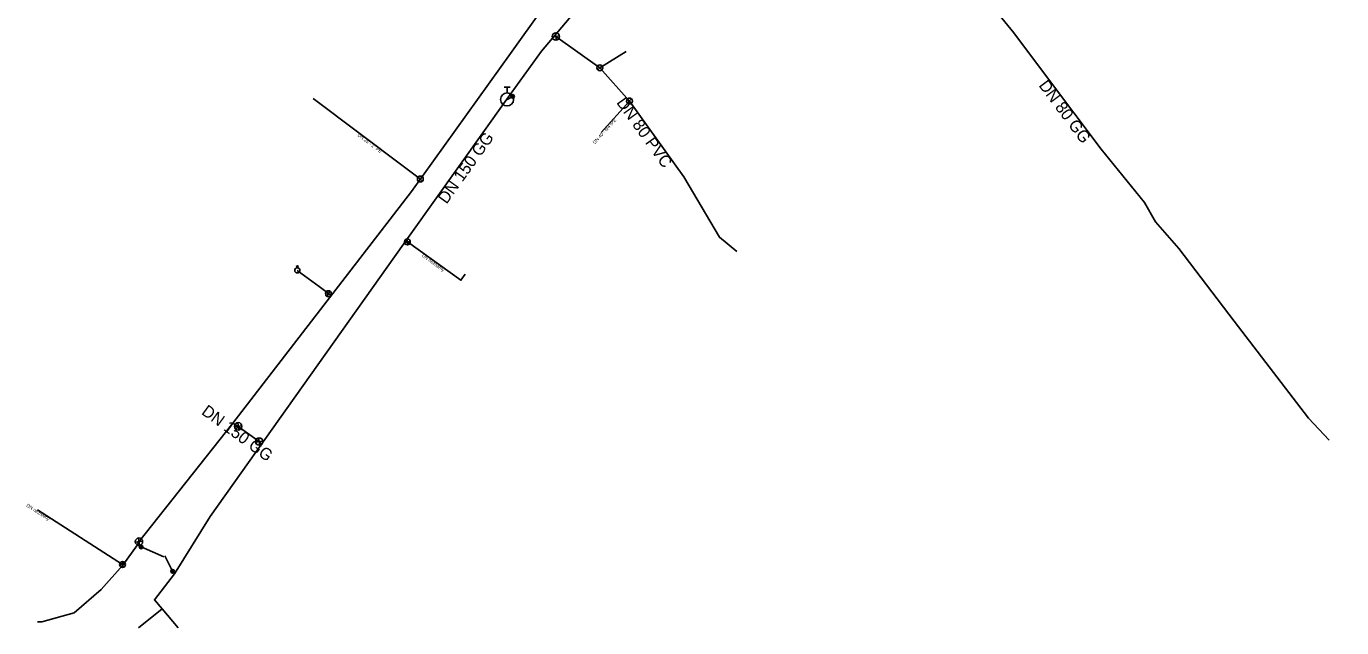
# Model space of a CAD drawing. Extents: x -4927528 to -4924018, y -11264917 to -11262544.
# Drawn here: x -4927528 to -4925742, y -11264917 to -11264100 of the extents above; entities that cross this region are included whole.
import ezdxf

# ---------------------------------------------------------------- set-up
doc = ezdxf.new("R2010")
doc.units = 0
for name, color, linetype in [('_hydrantova_odbocka_', 7, 'Continuous'), ('_kalosvod_', 7, 'Continuous'), ('_pripojka_prevzato_z_dokumentace_', 7, 'Continuous'), ('_pripojka_priblizne_', 7, 'Continuous'), ('_voda_smvak_prevzato_z_dokumentace_', 7, 'Continuous'), ('_voda_smvak_priblizne_', 7, 'Continuous'), ('Default', 7, 'Continuous'), ('MoLevel 2', 7, 'Continuous'), ('MoLevel 27', 7, 'Continuous'), ('MoLevel 28', 7, 'Continuous'), ('MoLevel 30', 7, 'Continuous'), ('MoLevel 32', 7, 'Continuous'), ('MoLevel 46', 7, 'Continuous'), ('MoLevel 53', 7, 'Continuous'), ('MoLevel 55', 7, 'Continuous')]:
    doc.layers.add(name, color=color, linetype=linetype)

# ---------------------------------------------------------------- blocks, each defined once
blk = doc.blocks.new('_uzaver_')
at = {"layer": 'Default'}
for p, q in [((-0.00035, -0.00035), (0.00035, 0.00035)), ((0.00035, -0.00035), (-0.00035, 0.00035))]:
    blk.add_line(p, q, dxfattribs=at)
for radius in [0.0005, 0.000025]:
    blk.add_circle((0, 0), radius, dxfattribs=at)
blk = doc.blocks.new('_uzaver_pripojka_')
at = {"layer": 'Default'}
for p, q in [((-0.00035, -0.00035), (0.00035, 0.00035)), ((0.00035, -0.00035), (-0.00035, 0.00035))]:
    blk.add_line(p, q, dxfattribs=at)
for radius in [0.0005, 0.000025]:
    blk.add_circle((0, 0), radius, dxfattribs=at)
blk = doc.blocks.new('_hydrant_voda_')
at = {"layer": 'Default'}
for p, q in [((-0.000225, 0.00095), (0.000225, 0.00095)), ((0, 0.00095), (0, 0.0005))]:
    blk.add_line(p, q, dxfattribs=at)
blk.add_circle((0, 0), 0.0005, dxfattribs=at)
blk = doc.blocks.new('_sachta_voda_')
at = {"layer": 'Default'}
blk.add_lwpolyline([(-0.0001, 0.00065), (0, 0.00035), (0.0001, 0.00065)], dxfattribs=at)
blk.add_circle((0, 0), 0.00035, dxfattribs=at)

msp = doc.modelspace()

# ---------------------------------------------------------------- linework, layer by layer
at = {"layer": '_hydrantova_odbocka_'}
msp.add_lwpolyline([(-4926870.9, -11264193.9), (-4926867.8, -11264195.4), (-4926875.4, -11264199.6)], dxfattribs=at)
at = {"layer": '_kalosvod_'}
for p, q in [((-4927372.5, -11264807.1), (-4927341.5, -11264820.7)), ((-4927329.7, -11264840.2), (-4927340.3, -11264819.1))]:
    msp.add_line(p, q, dxfattribs=at)
at = {"layer": '_pripojka_prevzato_z_dokumentace_'}
for p, q in [((-4927014.7, -11264291.5), (-4927138.7, -11264198.4)), ((-4926993.2, -11264307.6), (-4927014.7, -11264291.5)), ((-4927513.4, -11264756.6), (-4927397.6, -11264831)), ((-4927397.6, -11264831), (-4927397.1, -11264831.8))]:
    msp.add_line(p, q, dxfattribs=at)
msp.add_lwpolyline([(-4927012.9, -11264391.7), (-4927010.8, -11264393), (-4926938.1, -11264445.1), (-4926932.3, -11264437)], dxfattribs=at)
at = {"layer": '_pripojka_priblizne_'}
for p, q in [((-4926749.4, -11264156.5), (-4926713.7, -11264134.4)), ((-4926709.2, -11264201.7), (-4926747.6, -11264244.3)), ((-4927130.8, -11264453.7), (-4927160.3, -11264431.6))]:
    msp.add_line(p, q, dxfattribs=at)
msp.add_lwpolyline([(-4927114.6, -11264466.2), (-4927118.1, -11264463.2), (-4927130.8, -11264453.7)], dxfattribs=at)
at = {"layer": '_voda_smvak_prevzato_z_dokumentace_'}
for p, q in [((-4927375.4, -11264800), (-4927377.2, -11264804.4)), ((-4927377.2, -11264804.4), (-4927372.5, -11264807.1)), ((-4927329.7, -11264840.2), (-4927326.9, -11264843.6)), ((-4927376, -11264916.8), (-4927344, -11264891.3)), ((-4927344, -11264891.3), (-4927322.3, -11264916.8))]:
    msp.add_line(p, q, dxfattribs=at)
for points in [[(-4925741.8, -11263257.7), (-4926471.3, -11263779.7), (-4926626.3, -11263906.7), (-4926783.8, -11264042.7), (-4926826.3, -11264075.2), (-4926870.7, -11264137), (-4927005.3, -11264324.4), (-4927247.9, -11264639.2), (-4927375.4, -11264800)], [(-4926437.3, -11263792.5), (-4926527.5, -11263855.5), (-4926618.2, -11263919.4), (-4926768.5, -11264062.5), (-4926828.7, -11264133.9), (-4926875.7, -11264199.1), (-4927006, -11264381.9), (-4927278.6, -11264765.7), (-4927326.9, -11264843.6)], [(-4925759, -11264662.1), (-4925786.7, -11264632.1), (-4925887.7, -11264500.4), (-4925963.1, -11264402.1), (-4925994.9, -11264365.7), (-4926009.6, -11264339.3), (-4926068.7, -11264267.1), (-4926142.6, -11264168.2), (-4926187.3, -11264109.2), (-4926252.4, -11264029.2), (-4926261.4, -11264017.3), (-4926383.4, -11263863.6), (-4926433.6, -11263797)], [(-4926809.1, -11264114.1), (-4926749.4, -11264156.5), (-4926709.2, -11264201.7), (-4926635.4, -11264304.7), (-4926586.8, -11264386.6), (-4926563.3, -11264405.8)], [(-4927377.2, -11264804.4), (-4927397.1, -11264831.8), (-4927426.8, -11264865.1), (-4927463.4, -11264896.8), (-4927507.4, -11264908.9), (-4927513.4, -11264909)], [(-4927326.9, -11264843.6), (-4927354.4, -11264879.1), (-4927344, -11264891.3)]]:
    msp.add_lwpolyline(points, dxfattribs=at)
at = {"layer": '_voda_smvak_priblizne_'}
for p, q in [((-4926810.6, -11264112.4), (-4926809.1, -11264114.1)), ((-4927247.9, -11264639.2), (-4927240.5, -11264643.4)), ((-4927240.5, -11264643.4), (-4927212.1, -11264664.1)), ((-4927212.1, -11264664.1), (-4927208.9, -11264667.5))]:
    msp.add_line(p, q, dxfattribs=at)

# ---------------------------------------------------------------- block references
at = {"layer": 'MoLevel 27'}
for p, xscale, yscale, rotation in [((-4926809.1, -11264114.1), 10000, 10000.000000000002, -35.38533760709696), ((-4926867.8, -11264195.4), 5000, 5000, 180), ((-4927240.5, -11264643.4), 10000, 10000, -36.08730618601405), ((-4927212.1, -11264664.1), 10000, 9999.999999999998, 143.919102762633), ((-4927375.4, -11264800), 10000, 10000.000000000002, 51.5974476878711), ((-4927372.5, -11264807.1), 5000, 5000, -23.65856061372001), ((-4927329.7, -11264840.2), 5000, 5000, 139.93678707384)]:
    msp.add_blockref('_uzaver_', p, dxfattribs=dict(at, xscale=xscale, yscale=yscale, rotation=rotation))
at = {"layer": 'MoLevel 28', "xscale": 17636.684303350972, "yscale": 17636.684303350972, "rotation": -0.2784719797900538}
msp.add_blockref('_hydrant_voda_', (-4926875.4, -11264199.6), dxfattribs=at)
at = {"layer": 'MoLevel 30', "xscale": 10000, "yscale": 10000}
msp.add_blockref('_sachta_voda_', (-4927160.3, -11264431.6), dxfattribs=at)
at = {"layer": 'MoLevel 53', "xscale": 7999.999999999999, "yscale": 7999.999999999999}
for p in [(-4926749.4, -11264156.5), (-4926709.2, -11264201.7), (-4926993.2, -11264307.6)]:
    msp.add_blockref('_uzaver_pripojka_', p, dxfattribs=at)
at = {"layer": 'MoLevel 53'}
for p, xscale, yscale, rotation in [((-4927010.8, -11264393), 8000, 7999.999999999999, -35.49999999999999), ((-4927118.1, -11264463.2), 7999.999999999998, 8000, 14.900000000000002), ((-4927397.6, -11264831), 7999.999999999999, 8000, -41.50000000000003)]:
    msp.add_blockref('_uzaver_pripojka_', p, dxfattribs=dict(at, xscale=xscale, yscale=yscale, rotation=rotation))

# ---------------------------------------------------------------- texts
at = {"layer": 'MoLevel 2'}
msp.add_text('DN 150 GG', height=16.05, rotation=323.9127, dxfattribs=at).set_placement((-4927291.6, -11264626))
at = {"layer": 'MoLevel 32'}
msp.add_text('DN 40 - 6/4 IPE', height=4.55, rotation=47.9306, dxfattribs=at).set_placement((-4926756.1, -11264260.5))
at = {"layer": 'MoLevel 46'}
for s, rotation, p in [('DN 80 GG', 306.7678, (-4926154, -11264180.6)), ('DN 80 PVC', 305.6218, (-4926727.5, -11264203.8)), ('DN 150 GG', 54.5318, (-4926957.6, -11264342.5))]:
    msp.add_text(s, height=16.05, rotation=rotation, dxfattribs=at).set_placement(p)
at = {"layer": 'MoLevel 55'}
for s, rotation, p in [("DN 25 - 1'' PE", 323.1141, (-4927079, -11264249)), ('DN neznámý', 324.3596, (-4926991.7, -11264412.4)), ('DN neznámý', 327.2886, (-4927528.8, -11264752.1))]:
    msp.add_text(s, height=4.55, rotation=rotation, dxfattribs=at).set_placement(p)

doc.saveas('drawing.dxf')
